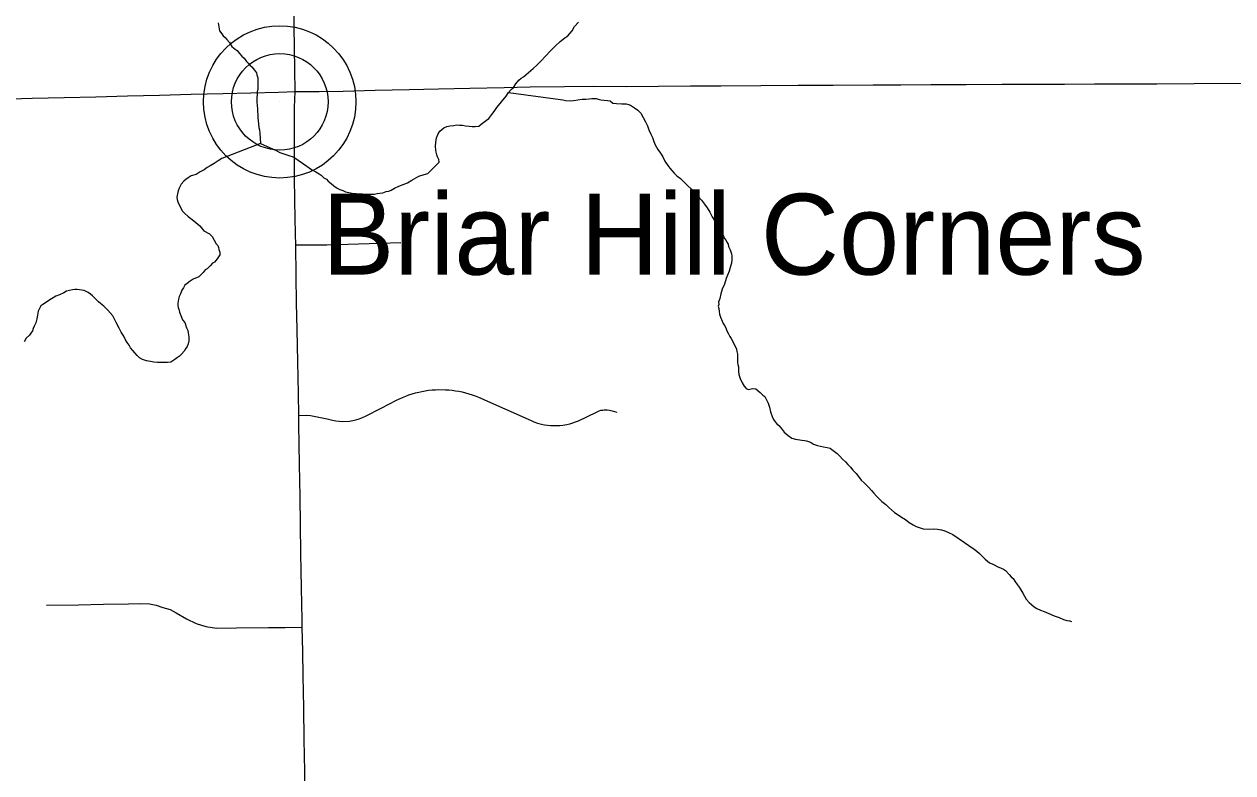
# Model space of a CAD drawing. Extents: x 103424 to 286016, y 38711 to 110967.
# Drawn here: x 106568 to 112838, y 63924 to 67809 of the extents above; entities that cross this region are included whole.
import ezdxf

# ---------------------------------------------------------------- set-up
doc = ezdxf.new("R2010")
doc.units = 0
for name, color, linetype in [('GM_X_County_Road', 7, 'Continuous'), ('GM_X_Major_River', 7, 'Continuous'), ('GM_X_Minor_River', 7, 'Continuous'), ('GM_X_State_Route', 7, 'Continuous'), ('GM_X_Township_Road', 7, 'Continuous'), ('GM_X_Unincorporated', 7, 'Continuous'), ('GM_X_Unincorporated_Location', 7, 'Continuous'), ('GM_X_Unincorporated_Text', 7, 'Continuous')]:
    doc.layers.add(name, color=color, linetype=linetype)

msp = doc.modelspace()

# ---------------------------------------------------------------- linework, layer by layer
at = {"layer": 'GM_X_County_Road'}
for points in [[(106445, 67420.6), (106610, 67424.7), (106775, 67428.8), (106940, 67433), (107105, 67437), (107270, 67441.2), (107435, 67445.3), (107600, 67449.4), (107743.4, 67453), (107886.9, 67456.5), (107973.2, 67459.6)], [(107973.2, 67459.6), (108098.3, 67460.8), (108223.4, 67462.1), (108388.4, 67466.8), (108565, 67470.9), (108717.1, 67474.4), (108880.2, 67477.3), (109058.1, 67480.3), (109192.4, 67483.8), (109370.3, 67485.5), (109523.7, 67487.1), (109691.7, 67486.5), (109858.6, 67487.1), (110024.2, 67488.9), (110181.2, 67489.5), (110389.2, 67490.8), (110583.6, 67492.6), (110765.1, 67493.4), (110971.2, 67494.4), (111116, 67494.7), (111270.6, 67496), (111454.6, 67496.8), (111638.6, 67497.5), (111801.8, 67498.1), (111964.3, 67498.7), (112120.1, 67499.3), (112270.4, 67499.9), (112443.3, 67500.6), (112637.2, 67501.2), (112902.1, 67502.4)]]:
    msp.add_lwpolyline(points, dxfattribs=at)
at = {"layer": 'GM_X_Major_River'}
for points in [[(109080.7, 67454.6), (109094.5, 67471), (109106.5, 67481.3), (109118.3, 67499.7), (109134.1, 67518.1), (109146, 67528.4), (109158, 67536.7), (109171.9, 67549), (109183.9, 67559.3), (109207.7, 67579.9), (109227.6, 67596.4), (109249.4, 67619), (109273.2, 67643.6), (109299, 67670.3), (109322.8, 67695), (109348.7, 67719.6), (109372.6, 67738.2), (109388.5, 67748.6), (109398.4, 67760.9), (109410.3, 67775.2), (109422, 67797.6), (109443.8, 67820.2)], [(107794.5, 67190.5), (107874.9, 67154), (107895.3, 67144.2), (107946, 67126.8), (107958.2, 67123), (107972.4, 67115.2), (107988.8, 67103.3), (108011.2, 67087.5), (108033.7, 67071.7), (108058.2, 67055.9), (108080.6, 67042.2), (108098.9, 67032.4), (108109.1, 67026.5), (108123.5, 67012.6), (108135.7, 67004.7), (108146, 66994.8), (108160.3, 66982.9), (108174.6, 66971), (108191, 66959.1), (108205.2, 66951.3), (108221.5, 66945.5), (108235.7, 66939.7), (108251.9, 66935.9), (108270.1, 66932.2), (108290.3, 66930.5), (108322.6, 66929), (108342.9, 66927.3), (108373.1, 66927.8), (108385.2, 66928), (108399.3, 66930.2), (108413.4, 66932.5), (108429.5, 66934.8), (108445.5, 66941.1), (108459.6, 66943.4), (108471.7, 66947.6), (108489.7, 66958), (108511.7, 66968.5), (108533.7, 66976.9), (108555.8, 66985.4), (108579.8, 66999.9), (108615.7, 67020.7), (108643.8, 67029.2), (108661.9, 67033.6), (108721.5, 67093.1), (108719.2, 67107.2), (108712.9, 67121.3), (108708.7, 67131.3), (108704.5, 67145.4), (108704.3, 67155.5), (108701.9, 67175.6), (108703.6, 67195.9), (108705.4, 67208), (108707.2, 67220.2), (108715, 67240.5), (108724.8, 67254.8), (108744.7, 67271.3), (108760.8, 67277.6), (108778.8, 67282), (108797, 67284.3), (108813.1, 67286.6), (108827.2, 67284.8), (108841.4, 67285), (108857.6, 67281.2), (108875.8, 67279.5), (108891.9, 67277.8), (108908.1, 67278), (108926.2, 67280.4), (108938.1, 67290.6), (108952.1, 67301), (108966, 67311.3), (108978, 67319.6), (108993.8, 67340.1), (109005.6, 67356.4), (109019.4, 67376.8), (109068.9, 67436.2), (109080.7, 67454.6)], [(107794.5, 67190.5), (107593.1, 67113), (107575.1, 67100.5), (107553.2, 67086), (107533.2, 67073.6), (107517.2, 67065.2), (107501.3, 67052.9), (107481.2, 67042.4), (107461.3, 67030), (107435.2, 67021.5), (107419.2, 67011.1), (107407.3, 67002.8), (107397.3, 66994.6), (107383.4, 66978.2), (107371.7, 66957.8), (107367.9, 66943.6), (107364.1, 66929.4), (107360.3, 66911.1), (107362.6, 66899.1), (107364.8, 66887), (107387.8, 66840.9), (107400.1, 66829), (107418.5, 66811.1), (107439, 66795.3), (107459.4, 66779.4), (107479.9, 66763.6), (107500.5, 66737.7), (107529, 66722), (107543.4, 66708.1), (107553.8, 66688), (107564.2, 66670), (107572.4, 66660.1), (107576.6, 66650), (107578.8, 66640), (107583.1, 66625.9), (107583.3, 66611.8), (107569.5, 66591.3), (107555.7, 66574.9), (107545.7, 66568.7), (107533.8, 66554.4), (107517.9, 66540), (107507.9, 66533.8), (107496, 66521.4), (107474.2, 66498.9), (107444.2, 66486.2), (107430.2, 66475.9), (107414.3, 66463.5), (107402.3, 66455.2), (107394.5, 66441), (107386.6, 66428.7), (107378.8, 66410.4), (107373, 66396.2), (107369.2, 66382), (107367.4, 66371.8), (107365.5, 66361.7), (107365.7, 66349.6), (107367.9, 66339.5), (107370.1, 66329.5), (107374.4, 66315.4), (107380.7, 66297.3), (107389.2, 66275.2), (107401.5, 66261.3), (107410.1, 66233.1), (107416.4, 66219.1), (107418.6, 66207), (107420.8, 66197), (107422.9, 66186.9), (107423.3, 66166.7), (107419.5, 66150.5), (107413.7, 66136.2), (107405.8, 66124), (107398, 66111.7), (107384.1, 66097.4), (107374.2, 66087.1), (107364.2, 66078.9), (107350.3, 66068.5), (107328.3, 66056), (107312.2, 66053.7), (107296, 66053.5), (107279.9, 66053.2), (107259.7, 66052.9), (107241.5, 66054.6), (107223.3, 66058.3), (107203.1, 66062.1), (107182.7, 66069.8), (107166.5, 66077.6), (107154.2, 66089.5), (107141.8, 66103.5), (107131.5, 66115.4), (107119.2, 66129.4), (107112.9, 66143.4), (107102.6, 66157.4), (107094.3, 66171.4), (107085.9, 66189.4), (107071.4, 66211.4), (107061, 66231.4), (107046.3, 66261.5), (107027.6, 66295.5), (107002.9, 66325.4), (106982.4, 66345.3), (106964, 66359.1)], [(106964, 66359.1), (106953.7, 66369.1), (106943.5, 66379), (106933.2, 66388.9), (106923, 66398.9), (106912.7, 66408.8), (106900.5, 66416.7), (106890.3, 66422.6), (106880.1, 66426.5), (106843.7, 66431.9), (106831.6, 66431.7), (106819.5, 66431.5), (106803.4, 66427.2), (106787.4, 66422.9), (106773.4, 66414.6), (106751.3, 66404.1), (106733.3, 66397.8), (106719.3, 66389.5), (106701.3, 66379.1), (106683.4, 66366.6), (106665.4, 66354.2), (106655.4, 66348), (106649.5, 66337.8), (106641.8, 66319.5), (106638.1, 66299.2), (106634.3, 66281), (106628.7, 66258.7), (106620.9, 66242.4), (106615, 66230.2), (106611.2, 66218), (106603.3, 66205.7), (106595.4, 66195.5), (106579.5, 66179.1), (106567.7, 66160.7)]]:
    msp.add_lwpolyline(points, dxfattribs=at)
at = {"layer": 'GM_X_Minor_River'}
for points in [[(107575.2, 67815.7), (107577.6, 67795.6), (107579.8, 67785.5), (107582, 67775.4), (107594.3, 67759.5), (107600.6, 67749.5), (107610.8, 67739.5), (107619.1, 67729.6), (107633.4, 67713.6), (107645.9, 67693.7), (107662.3, 67679.8), (107672.5, 67671.9), (107684.8, 67657.9), (107697.2, 67644), (107709.5, 67632.1), (107721.9, 67616.1), (107730.1, 67606.2), (107738.3, 67596.2), (107748.6, 67588.3), (107763, 67570.3), (107773.3, 67556.4)], [(107773.3, 67556.4), (107775.5, 67546.3), (107779.8, 67530.2), (107780, 67518.1), (107780.3, 67499.9), (107780.8, 67473.6), (107777, 67457.4), (107777.2, 67443.3), (107775.5, 67427.1), (107775.9, 67404.9), (107776.2, 67386.7), (107778.4, 67370.6), (107778.7, 67354.4), (107781, 67340.3), (107781.2, 67324.1), (107781.5, 67308), (107783.8, 67291.9), (107786.1, 67273.7), (107788.3, 67261.6), (107790.7, 67243.5), (107794.5, 67190.5)], [(109080.7, 67454.6), (109349.7, 67418.6), (109361.8, 67416.8), (109376, 67413), (109400.2, 67411.4), (109418.4, 67413.7), (109462.7, 67420.5), (109480.8, 67420.8), (109499, 67421.1), (109513, 67423.3), (109525.2, 67423.5), (109535.2, 67423.7), (109545.4, 67419.8), (109559.6, 67416), (109575.8, 67414.3), (109594, 67412.5), (109608.1, 67410.8), (109622.4, 67398.9), (109640.6, 67397.2), (109668.9, 67395.6), (109691.1, 67396), (109703.3, 67392.1), (109713.4, 67388.2), (109733.8, 67374.4), (109752.2, 67362.6), (109766.6, 67346.7), (109779.1, 67324.7), (109791.5, 67302.7), (109802, 67282.6), (109808.4, 67260.5), (109818.9, 67238.5), (109827.2, 67220.4), (109833.6, 67200.3), (109842, 67182.3), (109854.5, 67158.2), (109868.9, 67140.3), (109881.4, 67120.3), (109891.8, 67098.2), (109906.3, 67076.2), (109916.6, 67062.3), (109926.9, 67050.3), (109939.3, 67036.4), (109953.6, 67022.5), (109972, 67008.6), (109990.5, 66990.8), (110009, 66972.9), (110029.5, 66953), (110066.5, 66913.2), (110080.9, 66895.3), (110097.4, 66875.3), (110111.8, 66855.4), (110124.3, 66833.4), (110136.8, 66809.3), (110149.2, 66791.3), (110159.5, 66777.4), (110168, 66755.3), (110178.4, 66739.3), (110186.7, 66723.3), (110195, 66709.3), (110201.3, 66697.2), (110209.5, 66687.3), (110213.7, 66677.3), (110219.9, 66667.2), (110222.1, 66655.2), (110230.5, 66639.1), (110236.9, 66617), (110239.1, 66607), (110239.4, 66588.8), (110237.7, 66568.5), (110233.9, 66558.4), (110230, 66546.2), (110224.3, 66527.9), (110216.5, 66507.6), (110208.8, 66489.3), (110201.2, 66460.9), (110189.5, 66434.4), (110181.9, 66410), (110176.2, 66385.7), (110170.5, 66367.4), (110170.7, 66355.3), (110168.8, 66345.2), (110171, 66333.1), (110173.3, 66319), (110175.5, 66304.9), (110179.9, 66288.8), (110186.1, 66276.8), (110194.5, 66256.7), (110200.8, 66244.7), (110207, 66232.7), (110213.3, 66218.6), (110221.7, 66202.6), (110227.9, 66188.6), (110236.2, 66178.6), (110254.9, 66142.5), (110263.4, 66122.5), (110265.6, 66110.4), (110267.8, 66096.3), (110268.1, 66082.1), (110268.3, 66066), (110268.6, 66053.9), (110270.7, 66043.8)], [(110270.7, 66043.8), (110272.9, 66031.7), (110273.1, 66019.6), (110273.4, 66007.5), (110275.6, 65991.4), (110282, 65971.3), (110292.5, 65947.2), (110302.9, 65931.2), (110313.2, 65919.3), (110323.4, 65913.4), (110347.5, 65917.8), (110363.7, 65916), (110386.2, 65898.2), (110400.5, 65884.3), (110410.8, 65876.4), (110419.1, 65860.4), (110427.5, 65842.3), (110433.9, 65822.2), (110440.3, 65798.1), (110448.8, 65774), (110455.1, 65757.9), (110463.4, 65746), (110471.6, 65736), (110481.9, 65726.1), (110494.2, 65712.1), (110510.7, 65692.2), (110531.2, 65674.3), (110549.6, 65660.5), (110569.9, 65654.8), (110602.2, 65651.3), (110616.4, 65649.5), (110626.5, 65647.6), (110636.6, 65643.8), (110646.8, 65639.9), (110663.1, 65630), (110683.4, 65622.3), (110713.8, 65616.7), (110734, 65613), (110748.2, 65609.2), (110758.4, 65601.3), (110770.7, 65591.4), (110785, 65581.5), (110799.4, 65567.6), (110813.8, 65551.7), (110828.1, 65537.8), (110840.4, 65523.9), (110854.8, 65510), (110867.2, 65494), (110883.6, 65478.1), (110896, 65462.1), (110910.4, 65442.2), (110924.8, 65428.3), (110937.1, 65416.4), (110949.4, 65404.4), (110963.8, 65388.5), (110976.1, 65374.6), (110988.5, 65360.6), (111002.8, 65346.7), (111017.2, 65332.8), (111037.6, 65317), (111052, 65303.1), (111066.4, 65289.2), (111082.7, 65275.3), (111101.1, 65263.5), (111119.4, 65251.7), (111139.9, 65237.9), (111158.2, 65224), (111178.7, 65210.2), (111194.9, 65202.4), (111211.2, 65196.6), (111231.5, 65190.9), (111261.7, 65189.4), (111283.9, 65189.7), (111306.2, 65188.1), (111326.4, 65184.4), (111344.6, 65180.6), (111363, 65170.8), (111385.3, 65161.1), (111446.5, 65119.7), (111469, 65103.9), (111495.6, 65084.1), (111509.9, 65074.2), (111524.2, 65062.4), (111534.4, 65052.4), (111542.7, 65042.5), (111552.9, 65032.5), (111563.2, 65024.6), (111575.4, 65014.7), (111589.7, 65008.9), (111603.9, 65001), (111618.2, 64993.2), (111632.4, 64987.4), (111648.6, 64981.6), (111658.9, 64973.7), (111677.4, 64953.8), (111687.6, 64941.8), (111697.9, 64931.9), (111706.2, 64917.9), (111718.6, 64901.9), (111728.9, 64887.9), (111737.2, 64873.9)], [(111737.2, 64873.9), (111747.6, 64855.9), (111766.3, 64825.9), (111780.7, 64808), (111793, 64798.1), (111807.3, 64786.2), (111821.6, 64776.3), (111839.9, 64768.5), (111858.2, 64760.8), (111882.5, 64751.1), (111911, 64739.4), (111937.4, 64729.7), (111959.7, 64720), (111976, 64714.2), (111990.1, 64712.4), (111992.2, 64712.5), (111996.2, 64710.5), (112000.3, 64708.6)]]:
    msp.add_lwpolyline(points, dxfattribs=at)
at = {"layer": 'GM_X_State_Route'}
for points in [[(107973.2, 67459.6), (107971.5, 67573.4), (107969.8, 67687.2), (107969, 67798.2), (107968.2, 67909.3), (107968.8, 68074.3), (107969.3, 68239.4), (107969.5, 68925.4), (107970.9, 69085.6), (107970.6, 69155.8), (107971.9, 69218.2), (107972.7, 69319.7), (107974, 69484.7), (107974.9, 69587.9), (107975.7, 69691.1), (107976.9, 70473.6), (107977.7, 70638.7), (107978.1, 70743.1), (107978.6, 70847.5), (107979.2, 70905.7)], [(108026.4, 63767), (108023.9, 63931.6), (108021, 64096.6), (108018.2, 64261.7), (108015.3, 64426.7), (108013.1, 64553.2), (108010.9, 64679.6), (108010.3, 64718.3), (108006.8, 64883.3), (108004.9, 64973), (108003, 65062.6), (108001.1, 65210.5), (107999.1, 65358.4), (107996.4, 65523.4), (107994.7, 65627.7), (107993, 65731.9), (107992.7, 65779.3), (107990.8, 65893.4), (107987.5, 66058.4), (107984.1, 66223.4), (107981.3, 66362.6), (107978.5, 66501.8), (107978.1, 66664.3), (107976, 66719.6), (107974.3, 66805.9), (107972.6, 66892.2), (107971.3, 67017.4), (107970.4, 67117.6), (107969.8, 67213.8), (107971.3, 67376.1), (107973.2, 67459.6)]]:
    msp.add_lwpolyline(points, dxfattribs=at)
at = {"layer": 'GM_X_Township_Road'}
for points in [[(107978.1, 66664.3), (108137.7, 66664.9), (108302.7, 66669.8), (108412.4, 66673), (108522, 66676.3)], [(107992.7, 65779.3), (108032.9, 65779.9), (108053, 65778.6), (108140.2, 65760.4), (108167.7, 65754), (108184.8, 65750.6), (108202.4, 65748.4), (108219.8, 65747.5), (108255, 65749.4), (108272.4, 65752.1), (108289.5, 65756), (108306.1, 65761.1), (108322.5, 65767.4), (108339.6, 65775.3), (108419.4, 65816.3), (108499.3, 65857.4), (108515.1, 65865.2), (108531.3, 65872.4), (108547.4, 65879), (108564, 65885.1), (108580.6, 65890.6), (108597.4, 65895.4), (108614.6, 65899.8), (108631.7, 65903.5), (108649.1, 65906.6), (108666.4, 65909.1), (108683.8, 65911), (108701.4, 65912.3), (108718.8, 65913), (108754, 65912.5), (108771.7, 65911.3), (108789, 65909.6), (108806.4, 65907.2), (108823.7, 65904.2), (108840.9, 65900.6), (108858, 65896.4), (108874.9, 65891.6), (108891.7, 65886.3), (108908.3, 65880.3), (108924.4, 65873.8), (109060.8, 65812.9), (109197.3, 65752), (109211.8, 65746), (109231.7, 65739), (109252.1, 65733.5), (109267.7, 65730.4), (109283.3, 65728.1), (109298.9, 65726.5), (109314.8, 65725.8), (109346.5, 65726.8), (109362.1, 65728.6), (109383, 65732.2), (109398.4, 65735.9), (109413.5, 65740.4), (109428.3, 65745.7), (109442.9, 65751.6), (109537.2, 65796.5), (109551.2, 65802.1), (109559.6, 65805.3), (109569.1, 65806.8), (109576.9, 65807.5), (109592.7, 65807.1), (109604.8, 65805.9), (109618.8, 65803.4), (109643, 65795.3)], [(106684.9, 64793.5), (106849.9, 64796.7), (106979.5, 64799.2), (107109.1, 64801.7), (107170.5, 64802.2), (107218.9, 64800.8), (107252.9, 64793.5), (107288.3, 64782.7), (107325.1, 64771.1), (107356.9, 64754.5), (107411.1, 64723.4), (107461.1, 64698.3), (107510, 64683.4), (107566.8, 64674.7), (107669.8, 64675.8), (107834.9, 64677.7), (107922.9, 64678.6), (108010.9, 64679.6)]]:
    msp.add_lwpolyline(points, dxfattribs=at)
at = {"layer": 'GM_X_Unincorporated'}
for radius in [395.3, 250.6]:
    msp.add_circle((107894.1, 67406.1), radius, dxfattribs=at)
at = {"layer": 'GM_X_Unincorporated_Location'}
msp.add_line((107894.1, 67406.1), (107894.1, 67406.1), dxfattribs=at)

# ---------------------------------------------------------------- texts
at = {"layer": 'GM_X_Unincorporated_Text'}
msp.add_text('Briar Hill Corners', height=419.602, rotation=0.00001, dxfattribs=at).set_placement((108113.7, 66509.5))

doc.saveas('drawing.dxf')
